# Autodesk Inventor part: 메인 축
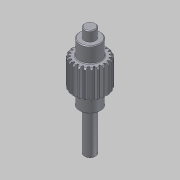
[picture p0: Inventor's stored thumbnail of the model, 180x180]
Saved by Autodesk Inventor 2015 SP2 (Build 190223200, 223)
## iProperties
Created: 2013-12
Part Number: 메인 축
Material: 강
Document SubType Name: Modeling
Designer: 한국산업디자인학원
Categories: <?xml version="1.0" encoding="UTF-16"?> <MemberInstance><Categories><FamilyTemplate><FamilyTemplateParameter ValueType="xs:double" Id="1" ObjectReferenceKey="da
Density: 1 g/cm^3
Appearance: 강철
CustomPartVersion: 1
Author: 한국산업디자인학원
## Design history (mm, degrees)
sketch "Sketch1"
  geometry: C1 r 12 at (0, 0)
  constraints: 1 centre point
  dimensions: "d0" = 24 diameter of C1 (= da_da)
extrude "Extrusion1" new body sketch "Sketch1" distance "d1" = 20 (= da_b); taper "d2" = 0 deg
workplane "Work Plane2"
feature "피치 지름" dims "d4" = 10, "d5" = 0
workplane "Work Plane8"
workplane "Work Plane9"
chamfer "모따기1" distance "d49" = 1; stored, may be unused: second distance "d50" = 2, angle "d51" = 45 deg
sketch "스케치3"
  geometry: C1 r 7.5 at (0, 0); 1 further point
  constraints: 1 centre point, 1 coincident
  dimensions: "d52" = 15 diameter of C1
extrude "돌출2" join sketch "스케치3" distance "d53" = 11; taper "d54" = 0 deg
sketch "스케치4"
  geometry: C1 r 4 at (0, 0); 1 further point
  constraints: 1 centre point, 1 coincident
  dimensions: "d55" = 8 diameter of C1
extrude "돌출3" join sketch "스케치4" distance "d56" = 7; taper "d57" = 0 deg
sketch "스케치5"
  geometry: C1 r 7.5 at (0, 0) reference; C2 r 7.5 at (0, 0) reference; 1 further point
extrude "돌출4" join sketch "스케치5" distance "d62" = 11; taper "d63" = 0 deg
sketch "스케치6"
  geometry: C1 r 4 at (0, 0); 1 further point
  constraints: 1 centre point, 1 coincident
  dimensions: "d64" = 8 diameter of C1
extrude "돌출5" join sketch "스케치6" distance "d65" = 30; taper "d66" = 0 deg
chamfer "모따기2" distance "d58" = 0.5; stored, may be unused: second distance "d59" = 2, angle "d60" = 45 deg
fillet "모깎기1" dims "d61" = 0.5
feature "스퍼 기어" dims "d34" = 1.428 (computed from da_z), "da_b" = 20, "da_d" = 22, "da_aw" = 31, "da_da" = 24, "da_df" = 19.5, "da_dw" = 22, angle "da_beta" = 0 deg, "da_lefttooth" = 0, "da_righttooth" = 0
body "Solid1"
sketch "Sketch2"
  geometry: C1 r 12 at (0, 0) reference; C2 r 11 at (0, 0)
  constraints: 1 centre point, 1 coincident
  dimensions: "d3" = 22 diameter of C2 (= da_dw)
body "Srf1"
node "투영된 루프1"
other parameters: "d16" = 31 (= da_aw), "d17" = 0, "d39" = 0, "d41" = 0, "d43" = 31 (= da_aw), "d46" = 31 (= da_aw), "d47" = 0, "d48" = 0
